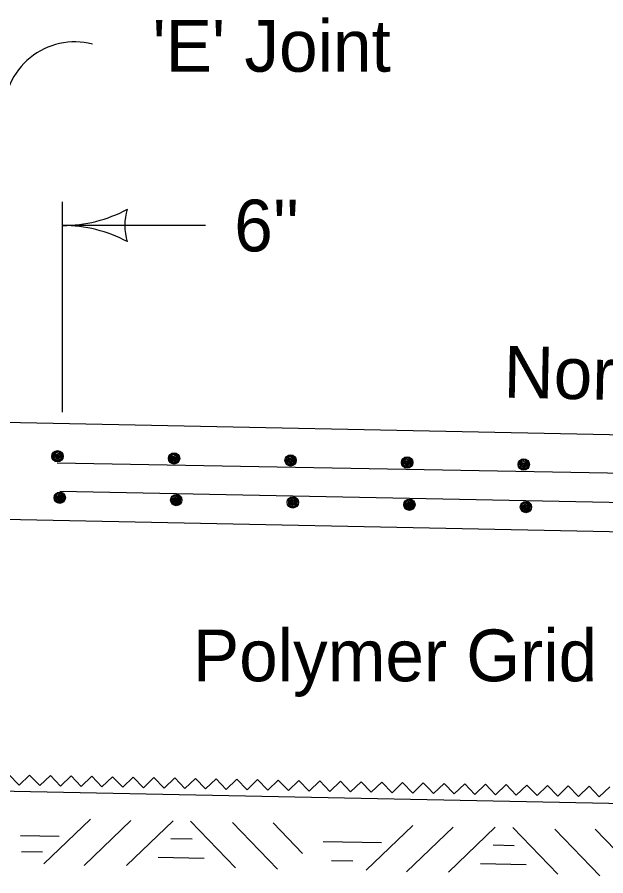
# Model space of a CAD drawing. Extents: x 10133 to 81668, y 7924 to 11018.
# Drawn here: x 10455.6 to 10637.4, y 8281.5 to 8546.9 of the extents above; entities that cross this region are included whole.
import ezdxf

# ---------------------------------------------------------------- set-up
doc = ezdxf.new("R2010")
doc.units = 0
doc.layers.add('BridgeExistingStructure', color=7, linetype='Continuous')
doc.layers.add('RasterAttachment', color=7, linetype='Continuous')

msp = doc.modelspace()

# ---------------------------------------------------------------- linework, layer by layer
at = {"layer": 'RasterAttachment'}
for p, q in [((10469.65, 8424.81), (10469.65, 8489.86)), ((10513.74, 8482.5), (10469.65, 8482.5)), ((10451.65, 8421.69), (11221.33, 8406.24)), ((10468.07, 8411.08), (10468.07, 8411.08)), ((10468, 8409.1), (11224.07, 8395.72)), ((10503.1, 8408.47), (10503.1, 8408.47)), ((10504.08, 8410.44), (10504.08, 8410.44)), ((10540.08, 8409.8), (10540.08, 8409.8)), ((10576.08, 8409.16), (10576.08, 8409.16)), ((10612.09, 8408.53), (10612.09, 8408.53)), ((11224.78, 8385.06), (10468.75, 8400.23)), ((10540.75, 8398.67), (10540.75, 8398.67)), ((10576.75, 8397.95), (10576.75, 8397.95)), ((10612.75, 8397.22), (10612.75, 8397.22)), ((10451.65, 8391.68), (11243.49, 8375.79)), ((10335.32, 8310), (11315.49, 8290.32)), ((10478.32, 8299.03), (10463.9, 8285.17)), ((10490.76, 8298.55), (10476.34, 8284.7)), ((10503.77, 8298.52), (10489.35, 8284.66)), ((10509.18, 8298.41), (10523.04, 8283.99)), ((10522.18, 8297.92), (10536.04, 8283.5)), ((10534.64, 8297.9), (10543.74, 8288.43)), ((10577.85, 8297.03), (10563.43, 8283.18)), ((10590.29, 8296.56), (10575.87, 8282.7)), ((10603.3, 8296.52), (10588.88, 8282.66)), ((10608.71, 8296.41), (10622.57, 8281.99)), ((10621.72, 8295.92), (10635.57, 8281.5)), ((10634.17, 8295.9), (10648.02, 8281.48))]:
    msp.add_line(p, q, dxfattribs=at)
for points in [[(10466.47, 8411.08), (10466.76, 8411.66), (10467.07, 8412.57), (10468.01, 8412.71), (10468.83, 8412.56), (10469.56, 8411.94), (10469.45, 8411.07), (10469.28, 8410.15), (10468.53, 8409.74), (10467.76, 8409.69), (10466.77, 8410.27), (10466.71, 8410.94), (10466.97, 8411.85), (10467.59, 8412.59), (10468.46, 8412.53), (10469.14, 8411.91), (10469.19, 8411.09), (10468.98, 8410.17), (10468.45, 8410.05), (10467.82, 8409.89), (10467.08, 8410.35), (10467.12, 8411.02), (10467.28, 8411.78), (10467.73, 8412.32), (10468.48, 8412.01), (10468.9, 8411.42), (10468.9, 8410.64), (10468.48, 8410.46), (10468, 8410.24), (10467.41, 8410.64), (10467.29, 8411.21), (10467.58, 8411.71), (10468.15, 8411.72), (10468.54, 8411.44), (10468.67, 8410.91), (10468.44, 8410.67), (10468.12, 8410.54), (10467.68, 8410.83), (10467.6, 8411.19), (10467.83, 8411.54), (10468.13, 8411.47), (10468.32, 8411.2), (10468.3, 8410.84), (10468.04, 8410.85), (10467.91, 8411.17)], [(10502.47, 8410.45), (10502.76, 8411.03), (10503.08, 8411.93), (10504.02, 8412.08), (10504.83, 8411.92), (10505.56, 8411.3), (10505.45, 8410.43), (10505.29, 8409.51), (10504.54, 8409.1), (10503.76, 8409.05), (10502.77, 8409.63), (10502.71, 8410.31), (10502.98, 8411.22), (10503.59, 8411.95), (10504.47, 8411.89), (10505.15, 8411.28), (10505.19, 8410.45), (10504.98, 8409.54), (10504.46, 8409.42), (10503.83, 8409.25), (10503.08, 8409.71), (10503.13, 8410.38), (10503.28, 8411.15), (10503.73, 8411.68), (10504.48, 8411.37), (10504.91, 8410.78), (10504.91, 8410), (10504.48, 8409.83), (10504, 8409.6), (10503.41, 8410), (10503.3, 8410.58), (10503.59, 8411.07), (10504.15, 8411.09), (10504.55, 8410.8), (10504.67, 8410.28), (10504.45, 8410.03), (10504.13, 8409.9), (10503.68, 8410.19), (10503.6, 8410.56), (10503.83, 8410.9), (10504.14, 8410.83), (10504.33, 8410.56), (10504.3, 8410.2), (10504.05, 8410.22), (10503.91, 8410.54)], [(10538.47, 8409.81), (10538.76, 8410.39), (10539.08, 8411.29), (10540.02, 8411.44), (10540.83, 8411.28), (10541.56, 8410.66), (10541.45, 8409.79), (10541.29, 8408.88), (10540.54, 8408.46), (10539.76, 8408.41), (10538.77, 8408.99), (10538.71, 8409.67), (10538.98, 8410.58), (10539.6, 8411.31), (10540.47, 8411.25), (10541.15, 8410.64), (10541.2, 8409.81), (10540.98, 8408.9), (10540.46, 8408.78), (10539.83, 8408.61), (10539.09, 8409.08), (10539.13, 8409.74), (10539.29, 8410.51), (10539.73, 8411.05), (10540.49, 8410.74), (10540.91, 8410.14), (10540.91, 8409.37), (10540.49, 8409.19), (10540.01, 8408.96), (10539.42, 8409.36), (10539.3, 8409.94), (10539.59, 8410.44), (10540.16, 8410.45), (10540.55, 8410.17), (10540.67, 8409.64), (10540.45, 8409.4), (10540.13, 8409.26), (10539.69, 8409.55), (10539.61, 8409.92), (10539.84, 8410.26), (10540.14, 8410.19), (10540.33, 8409.92), (10540.3, 8409.56), (10540.05, 8409.58), (10539.91, 8409.9)], [(10574.48, 8409.17), (10574.76, 8409.75), (10575.08, 8410.66), (10576.02, 8410.8), (10576.84, 8410.64), (10577.57, 8410.03), (10577.46, 8409.16), (10577.29, 8408.24), (10576.54, 8407.83), (10575.77, 8407.77), (10574.78, 8408.36), (10574.72, 8409.03), (10574.98, 8409.94), (10575.6, 8410.67), (10576.47, 8410.62), (10577.15, 8410), (10577.2, 8409.18), (10576.99, 8408.26), (10576.46, 8408.14), (10575.83, 8407.98), (10575.09, 8408.44), (10575.13, 8409.11), (10575.29, 8409.87), (10575.74, 8410.41), (10576.49, 8410.1), (10576.91, 8409.5), (10576.91, 8408.73), (10576.49, 8408.55), (10576.01, 8408.33), (10575.42, 8408.73), (10575.3, 8409.3), (10575.59, 8409.8), (10576.16, 8409.81), (10576.55, 8409.53), (10576.68, 8409), (10576.45, 8408.76), (10576.13, 8408.63), (10575.69, 8408.91), (10575.61, 8409.28), (10575.84, 8409.63), (10576.14, 8409.56), (10576.33, 8409.29), (10576.31, 8408.92), (10576.05, 8408.94), (10575.92, 8409.26)], [(10610.48, 8408.53), (10610.77, 8409.11), (10611.09, 8410.02), (10612.03, 8410.17), (10612.84, 8410.01), (10613.57, 8409.39), (10613.46, 8408.52), (10613.3, 8407.6), (10612.55, 8407.19), (10611.77, 8407.14), (10610.78, 8407.72), (10610.72, 8408.4), (10610.99, 8409.31), (10611.6, 8410.04), (10612.48, 8409.98), (10613.16, 8409.37), (10613.2, 8408.54), (10612.99, 8407.63), (10612.47, 8407.5), (10611.84, 8407.34), (10611.09, 8407.8), (10611.14, 8408.47), (10611.29, 8409.23), (10611.74, 8409.77), (10612.49, 8409.46), (10612.92, 8408.87), (10612.92, 8408.09), (10612.49, 8407.92), (10612.01, 8407.69), (10611.42, 8408.09), (10611.31, 8408.67), (10611.6, 8409.16), (10612.16, 8409.18), (10612.56, 8408.89), (10612.68, 8408.37), (10612.46, 8408.12), (10612.14, 8407.99), (10611.69, 8408.28), (10611.61, 8408.65), (10611.84, 8408.99), (10612.15, 8408.92), (10612.34, 8408.65), (10612.31, 8408.29), (10612.05, 8408.31), (10611.92, 8408.62)], [(10470.35, 8398.23), (10470.09, 8398.82), (10469.8, 8399.74), (10468.87, 8399.92), (10468.05, 8399.79), (10467.29, 8399.2), (10467.37, 8398.33), (10467.5, 8397.41), (10468.23, 8396.96), (10469.01, 8396.88), (10470.02, 8397.43), (10470.11, 8398.1), (10469.87, 8399.02), (10469.29, 8399.77), (10468.41, 8399.75), (10467.71, 8399.16), (10467.63, 8398.34), (10467.81, 8397.41), (10468.33, 8397.27), (10468.95, 8397.09), (10469.71, 8397.52), (10469.69, 8398.19), (10469.57, 8398.96), (10469.14, 8399.51), (10468.37, 8399.23), (10467.93, 8398.65), (10467.9, 8397.88), (10468.32, 8397.69), (10468.79, 8397.44), (10469.39, 8397.82), (10469.53, 8398.39), (10469.26, 8398.9), (10468.69, 8398.93), (10468.29, 8398.66), (10468.15, 8398.14), (10468.36, 8397.89), (10468.68, 8397.75), (10469.13, 8398.02), (10469.22, 8398.38), (10469.01, 8398.74), (10468.7, 8398.68), (10468.5, 8398.41), (10468.51, 8398.05), (10468.77, 8398.06), (10468.91, 8398.37)], [(10506.35, 8397.51), (10506.09, 8398.1), (10505.8, 8399.01), (10504.87, 8399.19), (10504.05, 8399.07), (10503.3, 8398.48), (10503.37, 8397.6), (10503.5, 8396.68), (10504.24, 8396.24), (10505.01, 8396.16), (10506.02, 8396.7), (10506.11, 8397.38), (10505.88, 8398.3), (10505.29, 8399.05), (10504.41, 8399.03), (10503.71, 8398.44), (10503.63, 8397.61), (10503.81, 8396.69), (10504.33, 8396.55), (10504.95, 8396.36), (10505.71, 8396.8), (10505.69, 8397.47), (10505.57, 8398.24), (10505.14, 8398.79), (10504.38, 8398.51), (10503.93, 8397.93), (10503.9, 8397.16), (10504.32, 8396.96), (10504.79, 8396.72), (10505.4, 8397.1), (10505.53, 8397.67), (10505.26, 8398.18), (10504.69, 8398.21), (10504.29, 8397.94), (10504.15, 8397.42), (10504.36, 8397.17), (10504.68, 8397.02), (10505.13, 8397.3), (10505.22, 8397.66), (10505.01, 8398.01), (10504.7, 8397.95), (10504.5, 8397.69), (10504.51, 8397.33), (10504.77, 8397.34), (10504.92, 8397.65)], [(10542.36, 8396.78), (10542.09, 8397.37), (10541.81, 8398.29), (10540.87, 8398.47), (10540.05, 8398.34), (10539.3, 8397.76), (10539.38, 8396.88), (10539.51, 8395.96), (10540.24, 8395.52), (10541.01, 8395.44), (10542.03, 8395.98), (10542.11, 8396.65), (10541.88, 8397.57), (10541.29, 8398.33), (10540.42, 8398.3), (10539.71, 8397.72), (10539.63, 8396.89), (10539.81, 8395.97), (10540.33, 8395.83), (10540.96, 8395.64), (10541.72, 8396.08), (10541.7, 8396.74), (10541.57, 8397.51), (10541.14, 8398.07), (10540.38, 8397.79), (10539.93, 8397.21), (10539.9, 8396.43), (10540.32, 8396.24), (10540.79, 8396), (10541.4, 8396.38), (10541.54, 8396.95), (10541.26, 8397.45), (10540.7, 8397.49), (10540.29, 8397.22), (10540.15, 8396.7), (10540.37, 8396.45), (10540.68, 8396.3), (10541.13, 8396.57), (10541.23, 8396.94), (10541.01, 8397.29), (10540.7, 8397.23), (10540.51, 8396.97), (10540.52, 8396.61), (10540.77, 8396.61), (10540.92, 8396.93)], [(10578.36, 8396.06), (10578.09, 8396.65), (10577.81, 8397.57), (10576.88, 8397.75), (10576.06, 8397.62), (10575.3, 8397.03), (10575.38, 8396.16), (10575.51, 8395.24), (10576.24, 8394.8), (10577.02, 8394.71), (10578.03, 8395.26), (10578.11, 8395.93), (10577.88, 8396.85), (10577.29, 8397.61), (10576.42, 8397.58), (10575.71, 8396.99), (10575.64, 8396.17), (10575.82, 8395.25), (10576.33, 8395.11), (10576.96, 8394.92), (10577.72, 8395.35), (10577.7, 8396.02), (10577.57, 8396.79), (10577.14, 8397.34), (10576.38, 8397.06), (10575.93, 8396.49), (10575.91, 8395.71), (10576.32, 8395.52), (10576.79, 8395.27), (10577.4, 8395.65), (10577.54, 8396.22), (10577.27, 8396.73), (10576.7, 8396.77), (10576.29, 8396.5), (10576.15, 8395.98), (10576.37, 8395.73), (10576.68, 8395.58), (10577.14, 8395.85), (10577.23, 8396.21), (10577.01, 8396.57), (10576.71, 8396.51), (10576.51, 8396.25), (10576.52, 8395.88), (10576.78, 8395.89), (10576.92, 8396.21)], [(10614.36, 8395.34), (10614.09, 8395.93), (10613.81, 8396.85), (10612.88, 8397.03), (10612.06, 8396.9), (10611.3, 8396.31), (10611.38, 8395.44), (10611.51, 8394.51), (10612.24, 8394.07), (10613.02, 8393.99), (10614.03, 8394.54), (10614.11, 8395.21), (10613.88, 8396.13), (10613.29, 8396.88), (10612.42, 8396.86), (10611.71, 8396.27), (10611.64, 8395.44), (10611.82, 8394.52), (10612.34, 8394.38), (10612.96, 8394.2), (10613.72, 8394.63), (10613.7, 8395.3), (10613.57, 8396.07), (10613.15, 8396.62), (10612.38, 8396.34), (10611.94, 8395.76), (10611.91, 8394.99), (10612.32, 8394.8), (10612.79, 8394.55), (10613.4, 8394.93), (10613.54, 8395.5), (10613.27, 8396.01), (10612.7, 8396.04), (10612.3, 8395.77), (10612.16, 8395.25), (10612.37, 8395), (10612.68, 8394.86), (10613.14, 8395.13), (10613.23, 8395.49), (10613.01, 8395.85), (10612.71, 8395.79), (10612.51, 8395.52), (10612.52, 8395.16), (10612.78, 8395.17), (10612.92, 8395.48)], [(10451.94, 8311.66), (10453.08, 8312.75), (10456.22, 8309.49), (10459.48, 8312.62), (10462.62, 8309.36), (10465.88, 8312.5), (10469.02, 8309.23), (10472.28, 8312.37), (10475.42, 8309.1), (10478.68, 8312.24), (10481.81, 8308.98), (10485.08, 8312.11), (10488.21, 8308.85), (10491.48, 8311.98), (10494.61, 8308.72), (10497.88, 8311.85), (10501.01, 8308.59), (10504.27, 8311.73), (10505.84, 8310.09)], [(10505.84, 8310.09), (10507.41, 8308.46), (10510.67, 8311.6), (10513.81, 8308.33), (10517.07, 8311.47), (10520.21, 8308.21), (10523.47, 8311.34), (10526.61, 8308.08), (10529.87, 8311.21), (10533, 8307.95), (10536.27, 8311.08), (10539.4, 8307.82), (10542.67, 8310.96), (10545.8, 8307.69), (10549.06, 8310.83), (10552.2, 8307.56), (10555.46, 8310.7), (10558.6, 8307.43), (10561.86, 8310.57), (10565, 8307.31), (10568.26, 8310.44), (10571.4, 8307.18), (10574.66, 8310.31), (10577.79, 8307.05), (10581.06, 8310.18), (10582.63, 8308.55)], [(10582.63, 8308.55), (10584.19, 8306.92), (10587.46, 8310.06), (10590.59, 8306.79), (10593.86, 8309.93), (10596.99, 8306.66), (10600.25, 8309.8), (10603.39, 8306.54), (10606.65, 8309.67), (10609.79, 8306.41), (10613.05, 8309.54), (10616.19, 8306.28), (10619.45, 8309.41), (10622.59, 8306.15), (10625.85, 8309.29), (10628.98, 8306.02), (10632.25, 8309.16), (10635.38, 8305.89), (10638.65, 8309.03)], [(10456.6, 8293.99), (10468.63, 8293.75)], [(10503.1, 8293.03), (10509.63, 8292.9)], [(10550.1, 8292.11), (10568.16, 8291.75)], [(10456.95, 8288.98), (10463.48, 8288.85)], [(10602.63, 8291.03), (10609.17, 8290.9)], [(10499.15, 8287.25), (10513.34, 8286.97)], [(10552.75, 8286.26), (10559.28, 8286.13)], [(10598.69, 8285.26), (10612.88, 8284.97)]]:
    msp.add_lwpolyline(points, dxfattribs=at)
for centre in [(10468.08, 8411.16), (10504.08, 8410.52), (10540.08, 8409.88), (10576.09, 8409.25), (10612.09, 8408.61), (10468.75, 8398.36), (10504.75, 8397.64), (10540.75, 8396.92), (10576.75, 8396.2), (10612.75, 8395.47)]:
    msp.add_circle(centre, 1.75, dxfattribs=at)
for centre, radius, start, end in [((10473.31, 8517.56), 21.69, 75.1725, 183.2908), ((10469.65, 8525), 42.5, 270, 298.0725), ((10469.65, 8525), 42.5, 270, 298.0725), ((10505.28, 8482.5), 16.42, 162.2666, 197.7334), ((10505.28, 8482.5), 16.42, 162.2666, 197.7334), ((10469.65, 8440), 42.5, 61.9275, 90), ((10469.65, 8440), 42.5, 61.9275, 90)]:
    msp.add_arc(centre, radius, start, end, dxfattribs=at)

# ---------------------------------------------------------------- texts
at = {"layer": 'BridgeExistingStructure'}
for s, p in [("'E' Joint", (10497.43, 8530.04)), ("6''", (10522.67, 8474.5)), ('Polymer Grid', (10509.92, 8341.61))]:
    msp.add_text(s, height=16, dxfattribs=at).set_placement(p)
msp.add_text('Normal Pavement Slope', height=16, rotation=358.8502, dxfattribs=at).set_placement((10605.77, 8429.29))

doc.saveas('drawing.dxf')
